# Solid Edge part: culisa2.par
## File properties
Author: Ionut
Template: Normal.par
Last saved by: Ionut
Revision: 3
Application: Solid Edge
Density: 7800.000 kg/m^3
Accuracy: 0.010
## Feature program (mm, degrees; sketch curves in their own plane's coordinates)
sketch for "unnamed Protrusion 1" plane through (0, 0, 0) normal (0, 0, 1) x-axis (1, 0, 0)
  line (-6, -15) -> (6, -15)
  line (6, -15) -> (6, 15)
  line (6, 15) -> (-6, 15)
  line (-6, 15) -> (-6, -15)
  dimension (linear) = 6
  dimension (linear) = 6
extrude "unnamed Protrusion 1" add finite 3 along +normal
sketch for "ExtrudedProtrusion_2" plane through (0, 0, 3) normal (0, 0, 1) x-axis (1, 0, 0)
  circle centre (0, 0) radius 2
extrude "ExtrudedProtrusion_2" add finite 4 along +normal
sketch for "ExtrudedProtrusion_3" plane through (0, -15, 1.5) normal (0, -1, 0) x-axis (1, 0, 0)
  circle centre (0, 0) radius 1
extrude "ExtrudedProtrusion_3" add finite 5 along +normal
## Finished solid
Body 1: solid body, 10 faces, 16 edges, 8 vertices.
  Faces by surface: plane 8, cylinder 2
  Edges by curve: line 12, circle 4
Bounding box of the edges (mm): 12.000 x 35.000 x 7.000, from (-6, -20, 0) to (6, 15, 7).
Cylindrical faces by radius (mm): R1 x1, R2 x1
Planar faces by outward normal: +x 1, +y 1, +z 2, -x 1, -y 2, -z 1
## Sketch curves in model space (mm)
circle centre (0, -15, 1.5) radius 1
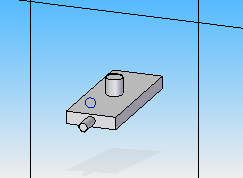
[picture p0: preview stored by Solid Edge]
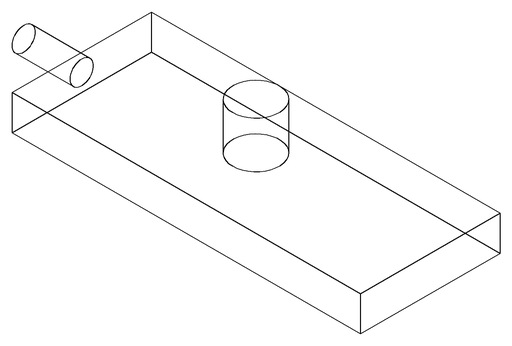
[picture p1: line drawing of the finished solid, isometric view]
